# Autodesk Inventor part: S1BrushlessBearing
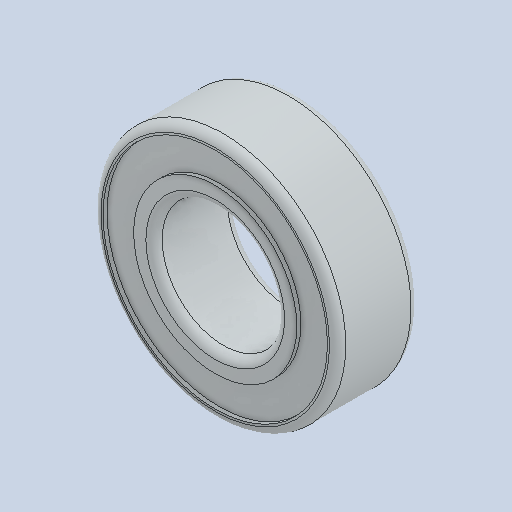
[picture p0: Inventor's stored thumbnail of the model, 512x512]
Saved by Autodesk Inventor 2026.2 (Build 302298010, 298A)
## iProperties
Created: 1601-01
Part Number: S1BrushlessBearing
Material: Chrome Stainless Steel
Document SubType Name: Modeling
Designer: mel
Density: 7.8 g/cm^3
Appearance: chromium plate
Author: mel
Sending System: SOLIDWORKS 2023
Part Number: Bearing
Last Saved Date: 2025-04-02
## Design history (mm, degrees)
fillet "Fillet1"
node "Solide1"
